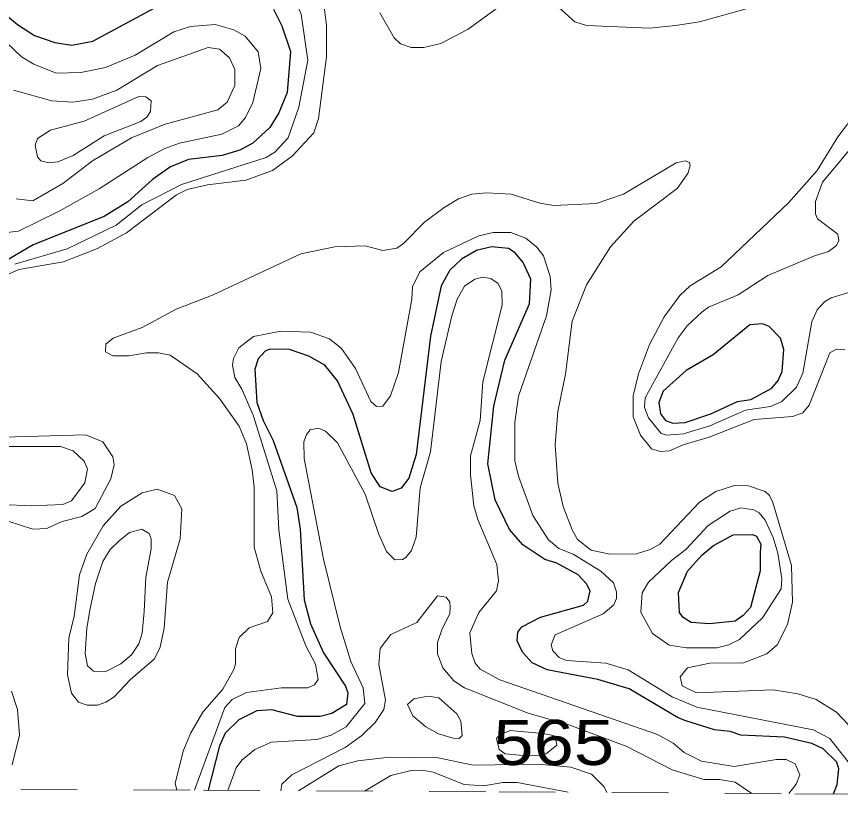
# Model space of a CAD drawing. Extents: x 577 to 602.9, y 7483.8 to 7511.6.
# Drawn here: x 587.677 to 589.137, y 7483.83 to 7485.238 of the extents above; entities that cross this region are included whole.
import ezdxf
from ezdxf.enums import TextEntityAlignment as Align

# ---------------------------------------------------------------- set-up
doc = ezdxf.new("R2010")
doc.units = 0
doc.header["$LTSCALE"] = 0.032
doc.linetypes.add('SHORT_DASHED', pattern=[2.7, 1.5, -1.2])
for name, color, linetype, lineweight in [('1', 7, 'Continuous', 25), ('2', 7, 'Continuous', 13), ('62', 7, 'SHORT_DASHED', 13)]:
    doc.layers.add(name, color=color, linetype=linetype, lineweight=lineweight)
doc.layers.add('61', color=7, linetype='Continuous')

msp = doc.modelspace()

# ---------------------------------------------------------------- linework, layer by layer
at = {"layer": '1'}
for points in [[(587.5061, 7485.3669), (587.6787, 7485.2238), (587.7089, 7485.2047), (587.7447, 7485.192), (587.7749, 7485.1872), (587.8123, 7485.1944), (587.9363, 7485.2612)], [(588.1319, 7485.2508), (588.147, 7485.2214), (588.1621, 7485.1761), (588.1566, 7485.1037), (588.1415, 7485.0672), (588.1256, 7485.0417), (588.0953, 7485.0139), (588.0723, 7485.0012), (588.0413, 7484.9916), (587.9816, 7484.9845), (587.9498, 7484.9717), (587.918, 7484.9495), (587.8743, 7484.9097), (587.8321, 7484.8835), (587.7065, 7484.8334), (587.6294, 7484.7889)], [(589.1246, 7483.8608), (589.1308, 7483.8774), (589.1338, 7483.9054), (589.1307, 7483.9173), (589.106, 7483.9404), (589.0861, 7483.9499), (589.0376, 7483.9611), (588.9605, 7483.9651), (588.9414, 7483.9714), (588.9136, 7483.9746), (588.8627, 7483.9905), (588.8492, 7483.9953), (588.7625, 7484.047), (588.7068, 7484.0637), (588.617, 7484.0804), (588.5907, 7484.0931), (588.5732, 7484.1122), (588.5637, 7484.132), (588.5653, 7484.1471), (588.5725, 7484.1567), (588.6051, 7484.1742), (588.6814, 7484.1949), (588.6893, 7484.202), (588.6933, 7484.2203), (588.687, 7484.233), (588.6718, 7484.2489), (588.6345, 7484.2696), (588.613, 7484.276), (588.574, 7484.3022), (588.5502, 7484.3292), (588.5247, 7484.3817), (588.512, 7484.4453), (588.5224, 7484.5479), (588.5422, 7484.629), (588.586, 7484.7292), (588.5884, 7484.7729), (588.5748, 7484.8024), (588.5605, 7484.8191), (588.5486, 7484.827), (588.5184, 7484.8302), (588.4921, 7484.8238), (588.4651, 7484.8079), (588.4444, 7484.7889), (588.4293, 7484.761), (588.4102, 7484.672), (588.3848, 7484.462), (588.3721, 7484.4199), (588.3586, 7484.4024), (588.3426, 7484.3968), (588.3212, 7484.4048), (588.3053, 7484.4294), (588.2735, 7484.5328), (588.2456, 7484.5924), (588.2234, 7484.6203), (588.1947, 7484.6362), (588.1606, 7484.6481), (588.1256, 7484.6489), (588.1176, 7484.6449), (588.1049, 7484.6314), (588.0993, 7484.6131), (588.1028, 7484.554), (588.1137, 7484.5221), (588.1316, 7484.487), (588.1733, 7484.3682), (588.1796, 7484.33), (588.1868, 7484.2044), (588.1979, 7484.1623), (588.221, 7484.1106), (588.2599, 7484.0517), (588.2639, 7484.0398), (588.2615, 7484.0191), (588.2353, 7484.0032), (588.2146, 7483.9977), (588.1749, 7483.9977), (588.1295, 7484.0096), (588.1025, 7484.008), (588.0707, 7483.9921), (588.0468, 7483.9682), (588.0365, 7483.946), (588.0164, 7483.8673)]]:
    msp.add_lwpolyline(points, dxfattribs=at)
for points in [[(588.9547, 7484.5562), (588.978, 7484.5598), (589.0154, 7484.5797), (589.0265, 7484.5932), (589.0337, 7484.6091), (589.0368, 7484.6481), (589.0305, 7484.668), (589.0106, 7484.6887), (588.9987, 7484.6934), (588.9764, 7484.6918), (588.9112, 7484.6386), (588.8635, 7484.6107), (588.8229, 7484.5742), (588.815, 7484.5543), (588.8182, 7484.5344), (588.8269, 7484.5225), (588.8396, 7484.5177), (588.8619, 7484.5185), (588.9072, 7484.5344)], [(588.9948, 7484.2887), (588.9947, 7484.2561), (588.9772, 7484.1909), (588.9645, 7484.1766), (588.9502, 7484.167), (588.9048, 7484.1623), (588.8722, 7484.1646), (588.8579, 7484.1734), (588.8516, 7484.1821), (588.85, 7484.2179), (588.8659, 7484.2553), (588.8913, 7484.2839), (588.912, 7484.3006), (588.947, 7484.3197), (588.9812, 7484.3205), (588.9883, 7484.3173), (588.9955, 7484.303)]]:
    msp.add_lwpolyline(points, close=True, dxfattribs=at)
at = {"layer": '2'}
for points in [[(587.9785, 7485.3447), (588.0301, 7485.3495), (588.0985, 7485.3288), (588.1279, 7485.3129), (588.1494, 7485.293), (588.1741, 7485.2588), (588.1812, 7485.2421), (588.1932, 7485.161), (588.1772, 7485.0775), (588.1582, 7485.0234), (588.1343, 7484.998), (588.1192, 7484.9884), (587.9689, 7484.9407), (587.8989, 7484.9042), (587.8536, 7484.8684), (587.7666, 7484.8266), (587.6738, 7484.7993)], [(587.6461, 7484.7745), (587.6811, 7484.7896), (587.7598, 7484.8032), (587.8202, 7484.827), (587.8719, 7484.8549), (587.9604, 7484.9223), (587.979, 7484.9317), (588.015, 7484.9399), (588.0834, 7484.9479), (588.1303, 7484.9654), (588.1653, 7484.9908), (588.2035, 7485.0322), (588.2122, 7485.0576), (588.2258, 7485.1666), (588.2258, 7485.2222), (588.2194, 7485.2747)], [(588.3204, 7485.2445), (588.3458, 7485.2), (588.357, 7485.1896), (588.376, 7485.1833), (588.3983, 7485.1833), (588.4285, 7485.1904), (588.477, 7485.2159), (588.5573, 7485.2747)], [(588.6154, 7485.2747), (588.6663, 7485.2286), (588.687, 7485.2222), (588.7983, 7485.2175), (588.8444, 7485.2222), (588.8873, 7485.2286), (588.9764, 7485.2532)], [(587.654, 7484.8549), (587.6803, 7484.858), (587.7526, 7484.893), (587.8234, 7484.9328), (587.9093, 7484.9884), (587.9395, 7485.0043), (587.9657, 7485.0139), (588.0405, 7485.0298), (588.0699, 7485.0441), (588.0826, 7485.0592), (588.0953, 7485.0855), (588.1097, 7485.1459), (588.1049, 7485.1753), (588.0818, 7485.2031), (588.0619, 7485.2143), (588.0286, 7485.2238), (587.9848, 7485.2206), (587.9554, 7485.2111), (587.887, 7485.1697), (587.8345, 7485.1475), (587.7908, 7485.1387), (587.7471, 7485.1379), (587.7073, 7485.1538), (587.6858, 7485.1666), (587.6318, 7485.2175)], [(587.6763, 7484.9153), (587.7057, 7484.9113), (587.759, 7484.9423), (587.8115, 7484.9821), (587.8806, 7485.0234), (587.9403, 7485.0473), (588.0333, 7485.0727), (588.05, 7485.0862), (588.0635, 7485.1157), (588.0635, 7485.1443), (588.054, 7485.165), (588.0365, 7485.1801), (588.0166, 7485.1833), (587.9268, 7485.1515), (587.8544, 7485.1077), (587.8115, 7485.0918), (587.7765, 7485.0862), (587.7391, 7485.0886), (587.6715, 7485.1077)], [(589.1649, 7485.0672), (589.1323, 7485.025), (589.0957, 7484.9654), (589.0448, 7484.9081), (588.9255, 7484.7944), (588.8706, 7484.761), (588.8524, 7484.7435), (588.8245, 7484.7062), (588.7983, 7484.6569), (588.7792, 7484.6052), (588.7697, 7484.5662), (588.7697, 7484.5288), (588.7824, 7484.4962), (588.8023, 7484.4724), (588.8182, 7484.4676), (588.8341, 7484.4684), (588.8579, 7484.4795), (588.9041, 7484.4927), (588.9839, 7484.5239), (589.0519, 7484.5296), (589.0702, 7484.536), (589.0814, 7484.5495), (589.1179, 7484.6425), (589.1299, 7484.6489), (589.145, 7484.6473)], [(589.1688, 7484.7547), (589.1203, 7484.7396), (589.1084, 7484.7324), (589.0957, 7484.7181), (589.0861, 7484.6974), (589.0702, 7484.606), (589.0591, 7484.5813), (589.0329, 7484.5559), (589.013, 7484.5471), (588.9685, 7484.5408), (588.9056, 7484.5129), (588.8587, 7484.4986), (588.8293, 7484.4962), (588.819, 7484.4994), (588.7967, 7484.5272), (588.7895, 7484.5455), (588.7911, 7484.5622), (588.8492, 7484.6688), (588.8651, 7484.6903), (588.8921, 7484.7149), (588.9032, 7484.7229), (588.9557, 7484.7451), (589.0082, 7484.7793), (589.0909, 7484.8143), (589.1156, 7484.8215), (589.1299, 7484.8326), (589.1338, 7484.8413), (589.1323, 7484.8525), (589.0965, 7484.8795), (589.0925, 7484.8882), (589.0925, 7484.9105), (589.1052, 7484.9447), (589.1649, 7485.0163)], [(587.9608, 7483.8676), (587.9582, 7483.8801), (587.9729, 7483.938), (587.9856, 7483.969), (588.0071, 7484.0056), (588.0421, 7484.0462), (588.0619, 7484.0811), (588.0651, 7484.0915), (588.0651, 7484.1177), (588.0715, 7484.1376), (588.089, 7484.1551), (588.1216, 7484.1662), (588.1311, 7484.1813), (588.1287, 7484.21), (588.1097, 7484.2553), (588.0977, 7484.2982), (588.0977, 7484.404), (588.0946, 7484.435), (588.0842, 7484.4811), (588.0715, 7484.5121), (588.0365, 7484.5614), (587.9967, 7484.6052), (587.949, 7484.6378), (587.9284, 7484.6425), (587.9069, 7484.6425), (587.8759, 7484.637), (587.8473, 7484.637), (587.8345, 7484.6441), (587.8353, 7484.6576), (587.848, 7484.668), (587.8997, 7484.6871), (587.9594, 7484.7197), (588.0254, 7484.7451), (588.1804, 7484.8175), (588.2409, 7484.8302), (588.2949, 7484.8318), (588.3259, 7484.8238), (588.3506, 7484.8278), (588.3625, 7484.8358), (588.3999, 7484.8739), (588.4349, 7484.8994), (588.4603, 7484.9153), (588.4834, 7484.9232), (588.5096, 7484.9256), (588.5534, 7484.9232), (588.6043, 7484.9073), (588.6289, 7484.9034), (588.7037, 7484.9065), (588.7522, 7484.9232), (588.846, 7484.9789), (588.8619, 7484.9821), (588.8691, 7484.9797), (588.8706, 7484.9733), (588.8667, 7484.9598), (588.8476, 7484.9336), (588.7705, 7484.8755), (588.7291, 7484.8302), (588.687, 7484.7626), (588.6615, 7484.6982), (588.6496, 7484.6044), (588.6361, 7484.5384), (588.6313, 7484.4795), (588.6361, 7484.4111), (588.6456, 7484.3698), (588.6615, 7484.3284), (588.6711, 7484.3117), (588.6949, 7484.2927), (588.7283, 7484.2855), (588.7752, 7484.2863), (588.7999, 7484.2935), (588.8166, 7484.303), (588.8873, 7484.3777), (588.916, 7484.3968), (588.9494, 7484.4072), (588.974, 7484.4064), (589.0034, 7484.3968), (589.0114, 7484.3897), (589.017, 7484.377), (589.0504, 7484.2656), (589.0519, 7484.2004), (589.0432, 7484.1607), (589.0249, 7484.1249), (589.0066, 7484.109), (588.9653, 7484.0931), (588.9056, 7484.0923), (588.8659, 7484.0843), (588.8531, 7484.0684), (588.8563, 7484.0525), (588.8818, 7484.0398), (589.0178, 7484.0454), (589.0615, 7484.0382), (589.0941, 7484.0279), (589.1299, 7484.0056), (589.1513, 7483.9833)], [(587.9924, 7483.8674), (588.046, 7484.0136), (588.0588, 7484.0279), (588.0842, 7484.0406), (588.1462, 7484.0485), (588.1924, 7484.0485), (588.2051, 7484.0541), (588.2114, 7484.0637), (588.2067, 7484.0907), (588.1892, 7484.1233), (588.1574, 7484.206), (588.1415, 7484.3284), (588.1383, 7484.3976), (588.0961, 7484.532), (588.0763, 7484.5781), (588.0635, 7484.5988), (588.0596, 7484.6203), (588.0612, 7484.6322), (588.0707, 7484.6513), (588.0969, 7484.6712), (588.1454, 7484.6807), (588.1979, 7484.6791), (588.2313, 7484.6672), (588.2528, 7484.6497), (588.2774, 7484.6147), (588.3045, 7484.5559), (588.3148, 7484.5471), (588.3259, 7484.5479), (588.3395, 7484.5662), (588.3538, 7484.6076), (588.3776, 7484.7372), (588.3784, 7484.7594), (588.3912, 7484.7857), (588.4333, 7484.8199), (588.4961, 7484.8493), (588.5216, 7484.8556), (588.5526, 7484.8556), (588.5796, 7484.8453), (588.5987, 7484.8294), (588.6106, 7484.8143), (588.6225, 7484.7777), (588.6241, 7484.7539), (588.6162, 7484.7077), (588.5661, 7484.5654), (588.5597, 7484.5193), (588.5597, 7484.4509), (588.5661, 7484.4239), (588.5915, 7484.3539), (588.6194, 7484.311), (588.6377, 7484.2958), (588.6631, 7484.2855), (588.7124, 7484.2553), (588.7347, 7484.2346), (588.7402, 7484.2187), (588.7402, 7484.2068), (588.7355, 7484.1957), (588.7164, 7484.1797), (588.6313, 7484.1424), (588.6241, 7484.1249), (588.6273, 7484.1145), (588.6385, 7484.1026), (588.6512, 7484.097), (588.7212, 7484.0923), (588.7609, 7484.0804), (588.8388, 7484.0326), (588.8826, 7484.0144), (589.0885, 7483.9746), (589.1179, 7483.9587), (589.1548, 7483.9124)], [(589.0454, 7483.8613), (589.0584, 7483.8778), (589.0647, 7483.8946), (589.0565, 7483.9142), (589.0405, 7483.9218), (589.0238, 7483.9218), (588.9484, 7483.9096), (588.8906, 7483.9188), (588.8601, 7483.934), (588.8403, 7483.9507), (588.8129, 7483.966), (588.5335, 7484.0629), (588.4985, 7484.0819), (588.4898, 7484.0923), (588.4834, 7484.1098), (588.4802, 7484.1464), (588.4961, 7484.1821), (588.5271, 7484.2203), (588.5311, 7484.2386), (588.5279, 7484.2672), (588.4945, 7484.3467), (588.4874, 7484.3714), (588.481, 7484.4263), (588.481, 7484.4596), (588.4985, 7484.5225), (588.5033, 7484.5909), (588.5375, 7484.7268), (588.5367, 7484.7515), (588.5303, 7484.765), (588.5176, 7484.7737), (588.5033, 7484.7761), (588.489, 7484.7729), (588.4707, 7484.7602), (588.4579, 7484.7372), (588.4484, 7484.7077), (588.4293, 7484.6266), (588.4102, 7484.4668), (588.3919, 7484.4032), (588.3848, 7484.3157), (588.3768, 7484.2919), (588.3665, 7484.2799), (588.3609, 7484.276), (588.3474, 7484.2752), (588.3323, 7484.2903), (588.318, 7484.3221), (588.2949, 7484.3921), (588.2456, 7484.4827), (588.2242, 7484.5034), (588.2122, 7484.509), (588.1971, 7484.5058), (588.1908, 7484.4978), (588.186, 7484.4843), (588.1868, 7484.4549), (588.221, 7484.2768), (588.2504, 7484.1567), (588.2695, 7484.0955), (588.291, 7484.0485), (588.2941, 7484.0207), (588.2607, 7483.9794), (588.2345, 7483.9651), (588.2091, 7483.9571), (588.1289, 7483.9523), (588.099, 7483.9397), (588.0762, 7483.9203), (588.0661, 7483.9068), (588.0514, 7483.8671)], [(588.1449, 7483.8665), (588.147, 7483.8781), (588.1647, 7483.8945), (588.2592, 7483.9428), (588.2886, 7483.9643), (588.3124, 7483.9873), (588.3275, 7484.0104), (588.3307, 7484.0271), (588.3188, 7484.0899), (588.3212, 7484.1185), (588.3403, 7484.1432), (588.3864, 7484.1646), (588.423, 7484.2116), (588.4381, 7484.2092), (588.4444, 7484.2004), (588.4452, 7484.1925), (588.4444, 7484.1797), (588.4309, 7484.1535), (588.423, 7484.1289), (588.423, 7484.109), (588.4325, 7484.0843), (588.4516, 7484.0613), (588.4707, 7484.0485), (588.5836, 7484.004), (588.6575, 7483.9825), (588.7585, 7483.9447), (588.8388, 7483.9035), (588.8945, 7483.8866), (588.9223, 7483.8866), (588.9505, 7483.8815), (588.9797, 7483.8616)], [(587.6691, 7483.9123), (587.6821, 7483.965), (587.6783, 7484.0105), (587.6678, 7484.0426)], [(588.1765, 7483.8663), (588.2482, 7483.9105), (588.2819, 7483.9194), (588.3379, 7483.9256), (588.4238, 7483.9245), (588.4858, 7483.9118), (588.6011, 7483.9134), (588.6591, 7483.9082), (588.6959, 7483.8959), (588.718, 7483.8731), (588.7226, 7483.8632)], [(588.6544, 7483.8636), (588.5637, 7483.8808), (588.5383, 7483.8808), (588.5049, 7483.8752), (588.4699, 7483.8776), (588.415, 7483.8991), (588.3959, 7483.903), (588.376, 7483.9022), (588.3403, 7483.8935), (588.2937, 7483.8657)]]:
    msp.add_lwpolyline(points, dxfattribs=at)
for points in [[(587.7964, 7485.0529), (587.8934, 7485.0966), (587.9061, 7485.0958), (587.9156, 7485.0886), (587.914, 7485.0695), (587.9077, 7485.06), (587.8973, 7485.0521), (587.8321, 7485.0266), (587.7773, 7484.9916), (587.7502, 7484.9805), (587.7343, 7484.9789), (587.72, 7484.9821), (587.7137, 7484.9892), (587.7097, 7485.0099), (587.7137, 7485.0218), (587.7367, 7485.0369)], [(587.6524, 7484.493), (587.7995, 7484.497), (587.8298, 7484.4843), (587.8473, 7484.4581), (587.8496, 7484.4437), (587.8441, 7484.4191), (587.8162, 7484.3666), (587.7924, 7484.3523), (587.7574, 7484.3436), (587.7304, 7484.3308), (587.7057, 7484.33), (587.596, 7484.365), (587.5483, 7484.3968), (587.5196, 7484.427), (587.4839, 7484.4525), (587.4711, 7484.466), (587.4664, 7484.4763), (587.4672, 7484.4843), (587.4783, 7484.4891), (587.5387, 7484.4891), (587.5809, 7484.4946)], [(587.6421, 7484.4763), (587.755, 7484.4763), (587.7773, 7484.4684), (587.7964, 7484.4501), (587.8027, 7484.4366), (587.798, 7484.4119), (587.7741, 7484.3801), (587.759, 7484.3738), (587.7033, 7484.3714), (587.6508, 7484.3738), (587.6079, 7484.3841), (587.561, 7484.4191), (587.5475, 7484.4334), (587.5443, 7484.4422), (587.5467, 7484.4549), (587.5673, 7484.4716), (587.6143, 7484.4779)], [(587.9387, 7484.1543), (587.9315, 7484.1209), (587.9212, 7484.1002), (587.8783, 7484.0629), (587.8496, 7484.0326), (587.8353, 7484.0231), (587.8202, 7484.0183), (587.8019, 7484.0183), (587.7868, 7484.0231), (587.7741, 7484.039), (587.7669, 7484.0716), (587.7693, 7484.1368), (587.7789, 7484.1758), (587.7884, 7484.2489), (587.8011, 7484.2855), (587.8306, 7484.3356), (587.8616, 7484.3706), (587.8997, 7484.3944), (587.926, 7484.4008), (587.957, 7484.3897), (587.9697, 7484.3658), (587.9665, 7484.3125), (587.9443, 7484.2362)], [(588.9605, 7484.3674), (588.9836, 7484.3642), (588.9931, 7484.3587), (589.0034, 7484.3459), (589.0178, 7484.3149), (589.0257, 7484.2871), (589.0329, 7484.2418), (589.0321, 7484.2243), (588.9987, 7484.1726), (588.9581, 7484.1344), (588.939, 7484.1249), (588.9176, 7484.1193), (588.8643, 7484.1193), (588.8333, 7484.1241), (588.8038, 7484.1448), (588.7832, 7484.1829), (588.7856, 7484.2171), (588.7967, 7484.2362), (588.8372, 7484.2744), (588.8627, 7484.2935), (588.9025, 7484.3364), (588.9414, 7484.3618)], [(587.9029, 7484.1837), (587.8997, 7484.1456), (587.8934, 7484.1265), (587.8806, 7484.1074), (587.8616, 7484.0915), (587.8337, 7484.0772), (587.8131, 7484.078), (587.8027, 7484.0875), (587.7987, 7484.1098), (587.8011, 7484.1543), (587.8075, 7484.1893), (587.817, 7484.2338), (587.8298, 7484.2728), (587.8425, 7484.2935), (587.8584, 7484.3094), (587.8767, 7484.3237), (587.8989, 7484.33), (587.9117, 7484.3221), (587.9156, 7484.3125), (587.9156, 7484.295), (587.9061, 7484.245)], [(588.4023, 7483.9794), (588.4245, 7483.9674), (588.4508, 7483.9595), (588.4611, 7483.9587), (588.4667, 7483.9643), (588.4643, 7483.9897), (588.4572, 7484.0024), (588.4253, 7484.031), (588.4063, 7484.0342), (588.3808, 7484.0295), (588.3697, 7484.0191), (588.3792, 7483.9992)], [(588.5684, 7483.9294), (588.543, 7483.9317), (588.5319, 7483.9396), (588.5271, 7483.9587), (588.5327, 7483.9651), (588.551, 7483.973), (588.6098, 7483.9677), (588.628, 7483.9645), (588.632, 7483.959), (588.634, 7483.9472), (588.616, 7483.9321), (588.6047, 7483.9287)]]:
    msp.add_lwpolyline(points, close=True, dxfattribs=at)
at = {"layer": '62'}
msp.add_lwpolyline([(587.4843, 7483.8703), (588.0082, 7483.8673), (588.532, 7483.8643), (589.0559, 7483.8612), (589.5798, 7483.8581), (590.1037, 7483.855), (590.6276, 7483.8519), (591.1515, 7483.8488), (591.6754, 7483.8456), (592.1993, 7483.8425), (592.7232, 7483.8393), (593.247, 7483.8361), (593.7709, 7483.8329), (594.2948, 7483.8296)], dxfattribs=at)

# ---------------------------------------------------------------- texts
at = {"layer": '61', "width": 1.2}
msp.add_text('565', height=0.08, dxfattribs=at).set_placement((588.6287, 7483.912), align=Align.CENTER)

doc.saveas('drawing.dxf')
